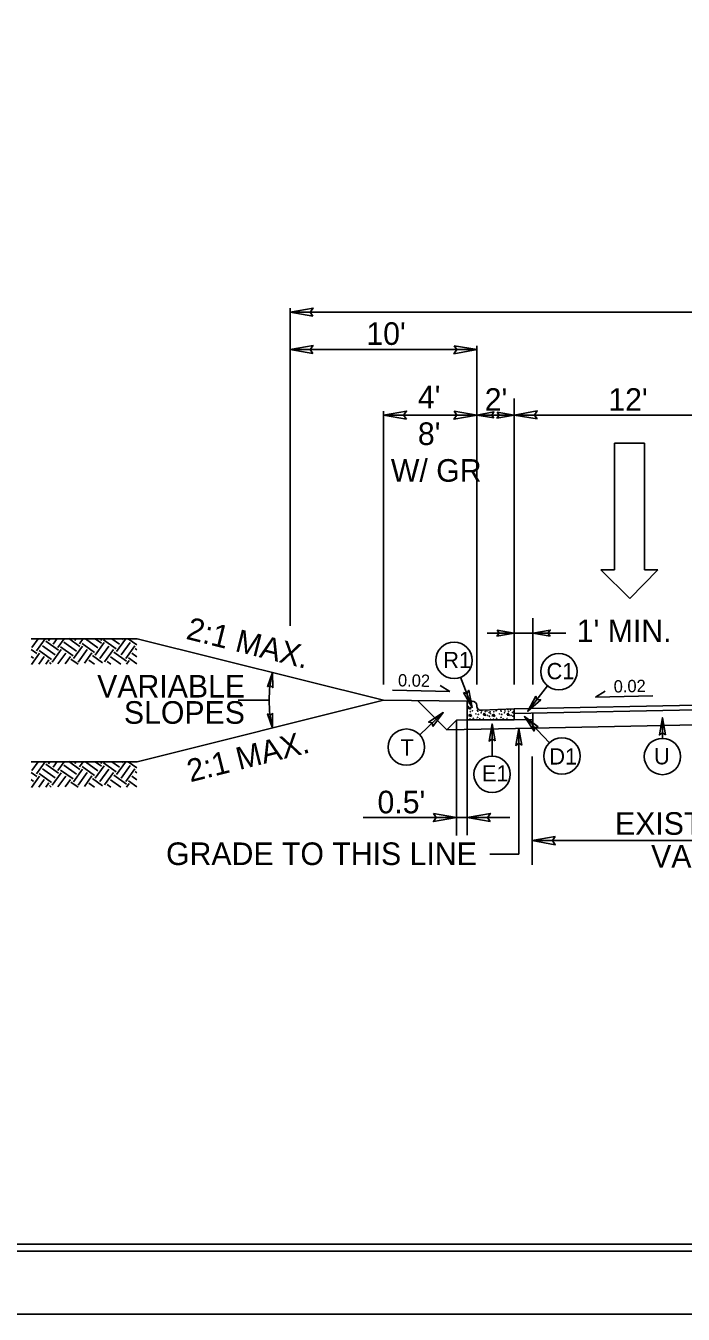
# Model space of a CAD drawing. Extents: x 3025871 to 3026431, y 707165 to 707825.
# Drawn here: x 3026115.2 to 3026150.3, y 707570.3 to 707639.3 of the extents above; entities that cross this region are included whole.
import ezdxf

# ---------------------------------------------------------------- set-up
doc = ezdxf.new("R2010")
doc.units = 0
for name, color, linetype in [('Old_Level_39', 7, 'Continuous'), ('Prop Drainage Structure Junction Box with Manhole CELL', 7, 'Continuous'), ('Prop Drainage Structure Junction Box with Slab Lid TB 840 34 CELL', 7, 'Continuous'), ('Prop Drainage Structure Plot Symbol 50 Scale', 7, 'Continuous'), ('Prop Pavement Schedule Description CELL', 7, 'Continuous'), ('Sheet Cutting Line CELL', 7, 'Continuous'), ('Sheet Data Field CELL', 7, 'Continuous'), ('Sheet Plot Border Inside CELL', 7, 'Continuous'), ('Sheet Sticker Incomplete CELL', 7, 'Continuous'), ('Sheet Typical CELL', 7, 'Continuous'), ('Typical Arrow Superelevation CELL', 7, 'Continuous'), ('Typical Grade Point Symbol CELL', 7, 'Continuous'), ('Typical Terminator CELL', 7, 'Continuous'), ('Typical Text Centerline CELL', 7, 'Continuous'), ('Typical Text Grade Point CELL', 7, 'Continuous')]:
    doc.layers.add(name, color=color, linetype=linetype)

msp = doc.modelspace()

# ---------------------------------------------------------------- linework, layer by layer
at = {"layer": 'Old_Level_39'}
msp.add_lwpolyline([(3026273.948, 707731.968), (3026023.973, 707731.968), (3026023.973, 707573.703), (3026273.948, 707573.703)], close=True, dxfattribs=at)
at = {"layer": 'Prop Drainage Structure Junction Box with Manhole CELL'}
msp.add_line((3026137.693, 707601.603), (3026142.298, 707601.696), dxfattribs=at)
at = {"layer": 'Prop Drainage Structure Junction Box with Slab Lid TB 840 34 CELL'}
for p, q in [((3026129.313, 707607.159), (3026129.313, 707624.159)), ((3026129.313, 707623.941), (3026223.827, 707623.941)), ((3026129.313, 707621.941), (3026139.313, 707621.941)), ((3026139.297, 707604.029), (3026139.297, 707622.152)), ((3026141.303, 707604.029), (3026141.303, 707619.333)), ((3026134.313, 707604.029), (3026134.313, 707618.653)), ((3026134.313, 707618.435), (3026139.313, 707618.435)), ((3026139.297, 707618.441), (3026141.303, 707618.441)), ((3026141.303, 707618.441), (3026206.819, 707618.441)), ((3026142.302, 707604.029), (3026142.302, 707607.582)), ((3026144.057, 707606.777), (3026139.864, 707606.777)), ((3026128.198, 707603.18), (3026126.542, 707603.18)), ((3026138.21, 707602.12), (3026138.21, 707595.956)), ((3026138.794, 707602.132), (3026138.794, 707595.968)), ((3026142.268, 707600.175), (3026142.268, 707594.384)), ((3026141.065, 707596.912), (3026133.223, 707596.912)), ((3026142.268, 707595.674), (3026164.202, 707595.674)), ((3026141.549, 707594.957), (3026139.999, 707594.957))]:
    msp.add_line(p, q, dxfattribs=at)
msp.add_arc((3026134.313, 707603.18), 6.116, 165.96376, 194.03624, dxfattribs=at)
at = {"layer": 'Prop Drainage Structure Plot Symbol 50 Scale'}
for p, q in [((3026138.794, 707602.132), (3026138.794, 707603.136)), ((3026138.794, 707603.136), (3026139.056, 707603.136)), ((3026138.831, 707602.756), (3026138.986, 707602.801)), ((3026138.969, 707602.71), (3026138.831, 707602.756)), ((3026138.958, 707602.436), (3026138.854, 707602.361)), ((3026138.854, 707602.361), (3026139.02, 707602.321)), ((3026139.02, 707602.321), (3026138.958, 707602.436)), ((3026138.986, 707602.801), (3026138.969, 707602.71)), ((3026139.296, 707602.885), (3026139.296, 707602.895)), ((3026141.303, 707602.717), (3026139.547, 707602.644)), ((3026139.702, 707602.493), (3026139.667, 707602.379)), ((3026139.667, 707602.379), (3026139.787, 707602.373)), ((3026139.787, 707602.373), (3026139.702, 707602.493)), ((3026140.211, 707602.436), (3026140.107, 707602.361)), ((3026140.107, 707602.361), (3026140.274, 707602.321)), ((3026140.274, 707602.321), (3026140.211, 707602.436)), ((3026140.955, 707602.493), (3026140.921, 707602.379)), ((3026140.921, 707602.379), (3026141.042, 707602.373)), ((3026141.042, 707602.373), (3026140.955, 707602.493)), ((3026141.303, 707602.132), (3026141.303, 707602.717)), ((3026138.794, 707602.132), (3026141.303, 707602.132))]:
    msp.add_line(p, q, dxfattribs=at)
for centre in [(3026138.808, 707603.025), (3026139.026, 707603.06), (3026138.859, 707602.842), (3026138.957, 707602.568), (3026139.077, 707602.619), (3026139.255, 707602.453), (3026139.335, 707602.647), (3026139.352, 707602.597), (3026139.381, 707602.425), (3026139.53, 707602.511), (3026139.558, 707602.613), (3026139.753, 707602.573), (3026139.851, 707602.616), (3026139.879, 707602.373), (3026139.96, 707602.533), (3026139.976, 707602.327), (3026140.016, 707602.568), (3026140.033, 707602.47), (3026140.211, 707602.568), (3026140.331, 707602.619), (3026140.508, 707602.453), (3026140.589, 707602.647), (3026140.606, 707602.597), (3026140.634, 707602.425), (3026140.783, 707602.511), (3026140.812, 707602.613), (3026140.961, 707602.676), (3026141.007, 707602.573), (3026141.104, 707602.659), (3026141.133, 707602.373), (3026141.213, 707602.533), (3026141.229, 707602.327), (3026141.269, 707602.568), (3026141.287, 707602.47), (3026138.94, 707602.178), (3026139.112, 707602.218), (3026139.289, 707602.155), (3026139.347, 707602.27), (3026139.461, 707602.184), (3026139.667, 707602.207), (3026139.828, 707602.138), (3026140.039, 707602.161), (3026140.193, 707602.178), (3026140.365, 707602.218), (3026140.543, 707602.155), (3026140.6, 707602.27), (3026140.715, 707602.184), (3026140.921, 707602.207), (3026141.081, 707602.138), (3026141.292, 707602.161)]:
    msp.add_circle(centre, 0.00805, dxfattribs=at)
for centre, start, end in [((3026139.056, 707602.895), 0, 90), ((3026139.537, 707602.885), 180, 272.38446)]:
    msp.add_arc(centre, 0.24, start, end, dxfattribs=at)
at = {"layer": 'Prop Pavement Schedule Description CELL'}
for p, q in [((3026141.303, 707602.717), (3026165.311, 707603.198)), ((3026141.303, 707602.467), (3026165.311, 707602.948)), ((3026142.298, 707601.696), (3026142.302, 707602.487)), ((3026141.303, 707602.134), (3026142.3, 707602.154)), ((3026142.298, 707601.696), (3026164.312, 707602.136))]:
    msp.add_line(p, q, dxfattribs=at)
at = {"layer": 'Sheet Cutting Line CELL'}
msp.add_lwpolyline([(3026272.073, 707731.586), (3026047.073, 707731.586), (3026047.073, 707574.086), (3026272.073, 707574.086)], close=True, dxfattribs=at)
at = {"layer": 'Sheet Data Field CELL'}
for p, q in [((3026146.666, 707610.158), (3026146.666, 707616.928)), ((3026146.666, 707616.928), (3026148.262, 707616.928)), ((3026148.262, 707616.928), (3026148.262, 707610.158)), ((3026147.489, 707608.635), (3026145.941, 707610.158)), ((3026145.941, 707610.158), (3026146.666, 707610.158)), ((3026148.988, 707610.158), (3026147.489, 707608.635)), ((3026148.262, 707610.158), (3026148.988, 707610.158))]:
    msp.add_line(p, q, dxfattribs=at)
at = {"layer": 'Sheet Plot Border Inside CELL'}
msp.add_line((3026138.21, 707602.12), (3026138.794, 707602.132), dxfattribs=at)
at = {"layer": 'Sheet Sticker Incomplete CELL'}
for p, q in [((3026137.861, 707603.657), (3026134.794, 707603.714)), ((3026137.861, 707603.657), (3026137.346, 707603.968)), ((3026145.647, 707603.356), (3026146.163, 707603.668)), ((3026145.647, 707603.356), (3026148.715, 707603.418))]:
    msp.add_line(p, q, dxfattribs=at)
at = {"layer": 'Sheet Typical CELL'}
for p, q in [((3026138.794, 707603.136), (3026134.313, 707603.18)), ((3026137.693, 707601.603), (3026136.135, 707603.162)), ((3026138.21, 707602.12), (3026137.693, 707601.603))]:
    msp.add_line(p, q, dxfattribs=at)
at = {"layer": 'Typical Grade Point Symbol CELL'}
for p, q in [((3026139.057, 707602.803), (3026138.433, 707604.411)), ((3026142.025, 707602.593), (3026143.09, 707603.95)), ((3026136.246, 707601.339), (3026137.503, 707602.519)), ((3026143.185, 707600.904), (3026141.846, 707602.307)), ((3026140.12, 707600.192), (3026140.119, 707601.917)), ((3026141.549, 707594.957), (3026141.544, 707601.68)), ((3026149.228, 707601.145), (3026149.227, 707602.246))]:
    msp.add_line(p, q, dxfattribs=at)
for centre in [(3026138.082, 707605.317), (3026143.691, 707604.714), (3026135.536, 707600.674), (3026143.856, 707600.2), (3026149.228, 707600.173), (3026140.12, 707599.22)]:
    msp.add_circle(centre, 0.972, dxfattribs=at)
at = {"layer": 'Typical Terminator CELL'}
msp.add_lwpolyline([(3026274.623, 707735.336), (3026022.023, 707735.336), (3026022.023, 707570.336), (3026274.623, 707570.336)], close=True, dxfattribs=at)
at = {"layer": 'Typical Text Centerline CELL'}
for points in [[(3026130.538, 707623.73), (3026129.313, 707623.941), (3026130.545, 707624.159), (3026130.389, 707623.941)], [(3026130.538, 707621.73), (3026129.313, 707621.941), (3026130.545, 707622.159), (3026130.389, 707621.941)], [(3026138.088, 707622.152), (3026139.313, 707621.941), (3026138.081, 707621.723), (3026138.238, 707621.941)], [(3026135.538, 707618.224), (3026134.313, 707618.435), (3026135.545, 707618.653), (3026135.389, 707618.435)], [(3026138.088, 707618.646), (3026139.313, 707618.435), (3026138.081, 707618.217), (3026138.238, 707618.435)], [(3026140.215, 707618.283), (3026139.297, 707618.441), (3026140.22, 707618.604), (3026140.103, 707618.441)], [(3026140.386, 707618.599), (3026141.305, 707618.441), (3026140.381, 707618.278), (3026140.499, 707618.441)], [(3026142.53, 707618.23), (3026141.305, 707618.441), (3026142.536, 707618.659), (3026142.38, 707618.441)], [(3026140.384, 707606.935), (3026141.303, 707606.777), (3026140.379, 707606.613), (3026140.496, 707606.777)], [(3026143.221, 707606.618), (3026142.302, 707606.777), (3026143.226, 707606.94), (3026143.108, 707606.777)], [(3026128.116, 707603.906), (3026128.38, 707604.663), (3026128.388, 707603.856), (3026128.266, 707603.979)], [(3026138.582, 707603.594), (3026139.057, 707602.803), (3026138.877, 707603.714), (3026138.768, 707603.547)], [(3026142.464, 707603.405), (3026142.025, 707602.593), (3026142.717, 707603.213), (3026142.518, 707603.221)], [(3026128.383, 707602.498), (3026128.38, 707601.696), (3026128.11, 707602.456), (3026128.265, 707602.38)], [(3026136.947, 707601.782), (3026137.503, 707602.519), (3026136.725, 707602.011), (3026136.921, 707601.973)], [(3026142.587, 707601.757), (3026141.846, 707602.307), (3026142.361, 707601.534), (3026142.397, 707601.73)], [(3026140.276, 707601.007), (3026140.119, 707601.917), (3026139.958, 707601.002), (3026140.119, 707601.118)], [(3026141.702, 707600.771), (3026141.544, 707601.68), (3026141.383, 707600.766), (3026141.545, 707600.882)], [(3026149.384, 707601.337), (3026149.227, 707602.246), (3026149.066, 707601.332), (3026149.228, 707601.448)], [(3026136.985, 707597.123), (3026138.21, 707596.912), (3026136.978, 707596.694), (3026137.135, 707596.912)], [(3026140.02, 707596.701), (3026138.794, 707596.912), (3026140.026, 707597.13), (3026139.87, 707596.912)], [(3026143.493, 707595.885), (3026142.268, 707595.674), (3026143.5, 707595.456), (3026143.343, 707595.674)]]:
    msp.add_lwpolyline(points, close=True, dxfattribs=at)
at = {"layer": 'Typical Text Grade Point CELL'}
for p, q in [((3026121.148, 707606.471), (3026115.464, 707606.471)), ((3026121.148, 707606.471), (3026115.464, 707606.471)), ((3026115.504, 707606.001), (3026115.842, 707606.471)), ((3026115.504, 707606.001), (3026115.842, 707606.471)), ((3026115.755, 707605.821), (3026116.222, 707606.471)), ((3026115.755, 707605.821), (3026116.222, 707606.471)), ((3026116.402, 707606.369), (3026116.475, 707606.471)), ((3026116.402, 707606.369), (3026116.475, 707606.471)), ((3026116.653, 707606.189), (3026116.864, 707606.483)), ((3026116.653, 707606.189), (3026116.864, 707606.483)), ((3026116.903, 707606.009), (3026117.235, 707606.471)), ((3026116.903, 707606.009), (3026117.235, 707606.471)), ((3026118.076, 707606.053), (3026117.48, 707606.481)), ((3026118.076, 707606.053), (3026117.48, 707606.481)), ((3026117.801, 707606.377), (3026117.875, 707606.48)), ((3026117.801, 707606.377), (3026117.875, 707606.48)), ((3026118.052, 707606.197), (3026118.255, 707606.479)), ((3026118.052, 707606.197), (3026118.255, 707606.479)), ((3026119.044, 707605.991), (3026118.376, 707606.471)), ((3026119.044, 707605.991), (3026118.376, 707606.471)), ((3026119.224, 707606.242), (3026118.897, 707606.477)), ((3026119.224, 707606.242), (3026118.897, 707606.477)), ((3026119.201, 707606.385), (3026119.266, 707606.476)), ((3026119.201, 707606.385), (3026119.266, 707606.476)), ((3026120.193, 707606.179), (3026119.782, 707606.474)), ((3026120.193, 707606.179), (3026119.782, 707606.474)), ((3026120.036, 707605.785), (3026120.517, 707606.453)), ((3026120.036, 707605.785), (3026120.517, 707606.453)), ((3026120.373, 707606.43), (3026120.313, 707606.473)), ((3026120.373, 707606.43), (3026120.313, 707606.473)), ((3026121.126, 707606.142), (3026120.667, 707606.472)), ((3026121.126, 707606.142), (3026120.667, 707606.472)), ((3026121.148, 707606.471), (3026134.313, 707603.18)), ((3026115.778, 707605.677), (3026115.464, 707605.903)), ((3026115.778, 707605.677), (3026115.464, 707605.903)), ((3026116.567, 707605.364), (3026115.898, 707605.844)), ((3026116.567, 707605.364), (3026115.898, 707605.844)), ((3026116.747, 707605.615), (3026116.078, 707606.095)), ((3026116.747, 707605.615), (3026116.078, 707606.095)), ((3026116.927, 707605.865), (3026116.258, 707606.346)), ((3026116.927, 707605.865), (3026116.258, 707606.346)), ((3026116.59, 707605.221), (3026117.07, 707605.889)), ((3026116.59, 707605.221), (3026117.07, 707605.889)), ((3026117.715, 707605.552), (3026117.047, 707606.033)), ((3026117.715, 707605.552), (3026117.047, 707606.033)), ((3026117.895, 707605.803), (3026117.227, 707606.283)), ((3026117.895, 707605.803), (3026117.227, 707606.283)), ((3026117.739, 707605.409), (3026118.219, 707606.077)), ((3026117.739, 707605.409), (3026118.219, 707606.077)), ((3026117.989, 707605.228), (3026118.47, 707605.897)), ((3026117.989, 707605.228), (3026118.47, 707605.897)), ((3026118.864, 707605.74), (3026118.196, 707606.221)), ((3026118.864, 707605.74), (3026118.196, 707606.221)), ((3026118.888, 707605.597), (3026119.368, 707606.265)), ((3026118.888, 707605.597), (3026119.368, 707606.265)), ((3026119.138, 707605.417), (3026119.618, 707606.085)), ((3026119.138, 707605.417), (3026119.618, 707606.085)), ((3026120.013, 707605.928), (3026119.344, 707606.409)), ((3026120.013, 707605.928), (3026119.344, 707606.409)), ((3026119.389, 707605.236), (3026119.869, 707605.905)), ((3026119.389, 707605.236), (3026119.869, 707605.905)), ((3026120.561, 707605.281), (3026119.893, 707605.761)), ((3026120.561, 707605.281), (3026119.893, 707605.761)), ((3026120.287, 707605.605), (3026120.767, 707606.273)), ((3026120.287, 707605.605), (3026120.767, 707606.273)), ((3026120.538, 707605.424), (3026121.018, 707606.093)), ((3026120.538, 707605.424), (3026121.018, 707606.093)), ((3026121.126, 707605.888), (3026121.041, 707605.949)), ((3026121.126, 707605.888), (3026121.041, 707605.949)), ((3026115.598, 707605.427), (3026115.464, 707605.523)), ((3026115.598, 707605.427), (3026115.464, 707605.523)), ((3026115.492, 707605.102), (3026115.922, 707605.701)), ((3026115.492, 707605.102), (3026115.922, 707605.701)), ((3026115.877, 707605.11), (3026116.172, 707605.521)), ((3026115.877, 707605.11), (3026116.172, 707605.521)), ((3026116.263, 707605.118), (3026116.423, 707605.341)), ((3026116.263, 707605.118), (3026116.423, 707605.341)), ((3026116.549, 707605.124), (3026116.446, 707605.197)), ((3026116.549, 707605.124), (3026116.446, 707605.197)), ((3026116.906, 707605.131), (3026117.321, 707605.709)), ((3026116.906, 707605.131), (3026117.321, 707605.709)), ((3026117.291, 707605.138), (3026117.572, 707605.529)), ((3026117.291, 707605.138), (3026117.572, 707605.529)), ((3026117.977, 707605.111), (3026117.595, 707605.385)), ((3026117.977, 707605.111), (3026117.595, 707605.385)), ((3026118.32, 707605.159), (3026118.72, 707605.717)), ((3026118.32, 707605.159), (3026118.72, 707605.717)), ((3026118.858, 707605.111), (3026118.564, 707605.322)), ((3026118.858, 707605.111), (3026118.564, 707605.322)), ((3026119.293, 707605.179), (3026118.744, 707605.573)), ((3026119.293, 707605.179), (3026118.744, 707605.573)), ((3026119.74, 707605.111), (3026119.532, 707605.26)), ((3026119.74, 707605.111), (3026119.532, 707605.26)), ((3026120.269, 707605.111), (3026119.713, 707605.511)), ((3026120.269, 707605.111), (3026119.713, 707605.511)), ((3026120.565, 707605.111), (3026120.705, 707605.304)), ((3026120.565, 707605.111), (3026120.705, 707605.304)), ((3026121.126, 707605.128), (3026120.681, 707605.448)), ((3026121.126, 707605.128), (3026120.681, 707605.448)), ((3026121.126, 707605.508), (3026120.861, 707605.699)), ((3026121.126, 707605.508), (3026120.861, 707605.699)), ((3026134.313, 707603.18), (3026121.148, 707599.888)), ((3026121.148, 707599.888), (3026115.464, 707599.888)), ((3026121.148, 707599.888), (3026115.464, 707599.888)), ((3026115.504, 707599.418), (3026115.842, 707599.888)), ((3026115.504, 707599.418), (3026115.842, 707599.888)), ((3026115.755, 707599.238), (3026116.222, 707599.888)), ((3026115.755, 707599.238), (3026116.222, 707599.888)), ((3026116.927, 707599.283), (3026116.258, 707599.763)), ((3026116.927, 707599.283), (3026116.258, 707599.763)), ((3026116.402, 707599.787), (3026116.475, 707599.888)), ((3026116.402, 707599.787), (3026116.475, 707599.888)), ((3026116.653, 707599.607), (3026116.864, 707599.9)), ((3026116.653, 707599.607), (3026116.864, 707599.9)), ((3026116.903, 707599.426), (3026117.235, 707599.888)), ((3026116.903, 707599.426), (3026117.235, 707599.888)), ((3026117.895, 707599.22), (3026117.227, 707599.701)), ((3026117.895, 707599.22), (3026117.227, 707599.701)), ((3026118.076, 707599.471), (3026117.48, 707599.898)), ((3026118.076, 707599.471), (3026117.48, 707599.898)), ((3026117.801, 707599.795), (3026117.875, 707599.897)), ((3026117.801, 707599.795), (3026117.875, 707599.897)), ((3026118.052, 707599.614), (3026118.255, 707599.896)), ((3026118.052, 707599.614), (3026118.255, 707599.896)), ((3026118.864, 707599.158), (3026118.196, 707599.638)), ((3026118.864, 707599.158), (3026118.196, 707599.638)), ((3026119.044, 707599.408), (3026118.376, 707599.889)), ((3026119.044, 707599.408), (3026118.376, 707599.889)), ((3026118.888, 707599.014), (3026119.368, 707599.682)), ((3026118.888, 707599.014), (3026119.368, 707599.682)), ((3026119.224, 707599.659), (3026118.897, 707599.894)), ((3026119.224, 707599.659), (3026118.897, 707599.894)), ((3026119.201, 707599.803), (3026119.266, 707599.893)), ((3026119.201, 707599.803), (3026119.266, 707599.893)), ((3026120.013, 707599.346), (3026119.344, 707599.826)), ((3026120.013, 707599.346), (3026119.344, 707599.826)), ((3026120.193, 707599.596), (3026119.782, 707599.892)), ((3026120.193, 707599.596), (3026119.782, 707599.892)), ((3026120.036, 707599.202), (3026120.517, 707599.871)), ((3026120.036, 707599.202), (3026120.517, 707599.871)), ((3026120.287, 707599.022), (3026120.767, 707599.69)), ((3026120.287, 707599.022), (3026120.767, 707599.69)), ((3026120.373, 707599.847), (3026120.313, 707599.89)), ((3026120.373, 707599.847), (3026120.313, 707599.89)), ((3026121.126, 707599.559), (3026120.667, 707599.889)), ((3026121.126, 707599.559), (3026120.667, 707599.889)), ((3026115.778, 707599.095), (3026115.464, 707599.321)), ((3026115.778, 707599.095), (3026115.464, 707599.321)), ((3026115.598, 707598.844), (3026115.464, 707598.941)), ((3026115.598, 707598.844), (3026115.464, 707598.941)), ((3026115.492, 707598.52), (3026115.922, 707599.118)), ((3026115.492, 707598.52), (3026115.922, 707599.118)), ((3026115.877, 707598.528), (3026116.172, 707598.938)), ((3026115.877, 707598.528), (3026116.172, 707598.938)), ((3026116.567, 707598.782), (3026115.898, 707599.262)), ((3026116.567, 707598.782), (3026115.898, 707599.262)), ((3026116.747, 707599.032), (3026116.078, 707599.513)), ((3026116.747, 707599.032), (3026116.078, 707599.513)), ((3026116.59, 707598.638), (3026117.07, 707599.306)), ((3026116.59, 707598.638), (3026117.07, 707599.306)), ((3026116.906, 707598.548), (3026117.321, 707599.126)), ((3026116.906, 707598.548), (3026117.321, 707599.126)), ((3026117.715, 707598.97), (3026117.047, 707599.45)), ((3026117.715, 707598.97), (3026117.047, 707599.45)), ((3026117.291, 707598.556), (3026117.572, 707598.946)), ((3026117.291, 707598.556), (3026117.572, 707598.946)), ((3026117.739, 707598.826), (3026118.219, 707599.494)), ((3026117.739, 707598.826), (3026118.219, 707599.494)), ((3026117.989, 707598.646), (3026118.47, 707599.314)), ((3026117.989, 707598.646), (3026118.47, 707599.314)), ((3026118.32, 707598.577), (3026118.72, 707599.134)), ((3026118.32, 707598.577), (3026118.72, 707599.134)), ((3026119.293, 707598.596), (3026118.744, 707598.991)), ((3026119.293, 707598.596), (3026118.744, 707598.991)), ((3026119.138, 707598.834), (3026119.618, 707599.502)), ((3026119.138, 707598.834), (3026119.618, 707599.502)), ((3026119.389, 707598.654), (3026119.869, 707599.322)), ((3026119.389, 707598.654), (3026119.869, 707599.322)), ((3026120.269, 707598.528), (3026119.713, 707598.928)), ((3026120.269, 707598.528), (3026119.713, 707598.928)), ((3026120.561, 707598.698), (3026119.893, 707599.179)), ((3026120.561, 707598.698), (3026119.893, 707599.179)), ((3026120.538, 707598.842), (3026121.018, 707599.51)), ((3026120.538, 707598.842), (3026121.018, 707599.51)), ((3026121.126, 707598.545), (3026120.681, 707598.865)), ((3026121.126, 707598.545), (3026120.681, 707598.865)), ((3026121.126, 707598.925), (3026120.861, 707599.116)), ((3026121.126, 707598.925), (3026120.861, 707599.116)), ((3026121.126, 707599.306), (3026121.041, 707599.367)), ((3026121.126, 707599.306), (3026121.041, 707599.367)), ((3026116.263, 707598.535), (3026116.423, 707598.758)), ((3026116.263, 707598.535), (3026116.423, 707598.758)), ((3026116.549, 707598.541), (3026116.446, 707598.614)), ((3026116.549, 707598.541), (3026116.446, 707598.614)), ((3026117.977, 707598.528), (3026117.595, 707598.802)), ((3026117.977, 707598.528), (3026117.595, 707598.802)), ((3026118.858, 707598.528), (3026118.564, 707598.74)), ((3026118.858, 707598.528), (3026118.564, 707598.74)), ((3026119.74, 707598.528), (3026119.532, 707598.677)), ((3026119.74, 707598.528), (3026119.532, 707598.677)), ((3026120.565, 707598.528), (3026120.705, 707598.722)), ((3026120.565, 707598.528), (3026120.705, 707598.722))]:
    msp.add_line(p, q, dxfattribs=at)

# ---------------------------------------------------------------- texts
at = {"layer": 'Prop Drainage Structure Junction Box with Slab Lid TB 840 34 CELL'}
for s, height, p in [("10'", 1.2089, (3026133.395, 707622.194)), ("4'", 1.2089, (3026136.151, 707618.802)), ("2'", 1.2089, (3026139.724, 707618.667)), ("12'", 1.2089, (3026146.332, 707618.667)), ("8'", 1.2089, (3026136.151, 707616.838)), ('W/ GR', 1.2089, (3026134.707, 707614.873)), ("1' MIN.", 1.2089, (3026144.645, 707606.292)), ("0.5'", 1.2089, (3026133.991, 707597.133)), ('EXIST. PAVEMENT', 1.20892, (3026146.691, 707595.986)), ('GRADE TO THIS LINE', 1.20892, (3026122.684, 707594.367)), ('VAR. WIDTH', 1.2089, (3026148.622, 707594.228))]:
    msp.add_text(s, height=height, dxfattribs=at).set_placement(p)
at = {"layer": 'Sheet Sticker Incomplete CELL'}
for s, rotation, p in [('0.02', 358.94076, (3026135.082, 707603.926)), ('0.02 ', 1.20285, (3026146.628, 707603.592))]:
    msp.add_text(s, height=0.6583, rotation=rotation, dxfattribs=at).set_placement(p)
at = {"layer": 'Typical Arrow Superelevation CELL'}
for s, p in [('R1', (3026137.508, 707604.901)), ('T', (3026135.215, 707600.227)), ('D1', (3026143.18, 707599.745))]:
    msp.add_text(s, height=0.87, rotation=360, dxfattribs=at).set_placement(p)
for s, p in [('C1', (3026143.03, 707604.308)), ('U', (3026148.78, 707599.753)), ('E1', (3026139.575, 707598.837))]:
    msp.add_text(s, height=0.87, dxfattribs=at).set_placement(p)
at = {"layer": 'Typical Text Grade Point CELL'}
for rotation, p in [(345.96376, (3026123.704, 707606.475)), (14.03624, (3026123.983, 707598.79))]:
    msp.add_text('2:1 MAX.', height=1.2089, rotation=rotation, dxfattribs=at).set_placement(p)
for s, p in [('VARIABLE', (3026119.002, 707603.328)), ('SLOPES', (3026120.431, 707601.925))]:
    msp.add_text(s, height=1.2089, dxfattribs=at).set_placement(p)

doc.saveas('drawing.dxf')
